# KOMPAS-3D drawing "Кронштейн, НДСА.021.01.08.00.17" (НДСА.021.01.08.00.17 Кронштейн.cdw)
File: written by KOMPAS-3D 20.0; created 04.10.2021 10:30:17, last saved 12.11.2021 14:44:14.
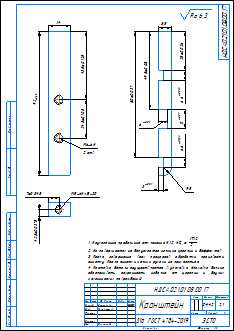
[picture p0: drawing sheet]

Sheet 1: A3, portrait

Document properties: Автор: adminzsc; Параметр неуказанной шероховатости: Ra 6,3; PLM_CDWXDTO: <item xmlns="http://appius.ru/pdm" xmlns:xs="http://www.w3.org/2001/XMLSchema" xmlns:xsi="http://www.w3.org/2001/XMLSchema-instance" xsi:type="item">  <element xmlns:d2p1="http://v8.1c.ru/8.1/data/enterprise/current-config" xsi:type="d2p1:CatalogRef.aps_Элемен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; PDM_DOCXDTO: <item xmlns="http://appius.ru/pdm" xmlns:xs="http://www.w3.org/2001/XMLSchema" xmlns:xsi="http://www.w3.org/2001/XMLSchema-instance" xsi:type="item">  <element xmlns:d2p1="http://v8.1c.ru/8.1/data/enterprise/current-config" xsi:type="d2p1:CatalogRef.aps_Элемен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; PDM_ITEMXDTO: <item xmlns="http://appius.ru/pdm" xmlns:xs="http://www.w3.org/2001/XMLSchema" xmlns:xsi="http://www.w3.org/2001/XMLSchema-instance" xsi:type="item">  <element xmlns:d2p1="http://v8.1c.ru/8.1/data/enterprise/current-config" xsi:type="d2p1:CatalogRef.aps_Элемен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; Масса: 0.0243981; PDM_DRAWINGXDTO: <item xmlns="http://appius.ru/pdm" xmlns:xs="http://www.w3.org/2001/XMLSchema" xmlns:xsi="http://www.w3.org/2001/XMLSchema-instance" xsi:type="item">  <element xmlns:d2p1="http://v8.1c.ru/8.1/data/enterprise/current-config" xsi:type="d2p1:CatalogRef.aps_Элемен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

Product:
- Part/product: Кронштейн  | designation НДСА.021.01.08.00.17
    Материал: Д16  ГОСТ 4784-2019 (density 2800 kg/m3)
    Масса: 0.0243981
    additional columns: <item xmlns="http://appius.ru/pdm" xmlns:xs="http://www.w3.org/2001/XMLSchema" x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; <item xmlns="http://appius.ru/pdm" xmlns:xs="http://www.w3.org/2001/XMLSchema" x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; <item xmlns="http://appius.ru/pdm" xmlns:xs="http://www.w3.org/2001/XMLSchema" x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
    source file: НДСА.021.01.08.00.17 Кронштейн.cdw

Title block, sheet 1: Наименование: Кронштейн; designation: НДСА.021.01.08.00.17; Материал: Д16  ГОСТ 4784-2019; Масса: 24,4 г; Количество листов документа: 1; organisation: ЭСТО; Форматы листов документа: A3; stored path: C:\Users\korychko\Desktop\PLM\НДСА.021.01.08.00.17 Кронштейн.cdw; Разработал: Васильева; Проверил: Горностаев; Утвердил: Белецкий; Разработал, date: 04.10.2021

Views: Вид 1, Спереди, Проекционный вид 3, Проекционный вид 4
Referenced files in C:\Users\vasilyeva\Desktop\PM_APPIUS\: НДСА.021.01.08.00.17 Кронштейн.m3d
Referenced files in C:\Users\korychko\Desktop\PLM\: НДСА.021.01.08.00.17 Кронштейн.m3d
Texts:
  JS12
  JS11
  JS9
  Ra 6,3
  НДСА.021.01.08.00.17 Кронштейн
Dimensions and other numbers on the sheet: 14; 43,5±0,125; 24,5±0,105; 92; 2 отв.; 7±0,045; 4,25±0,0375; 8,5; 25±0,026; 49,8±0,08; 80±0,037; 5; 6,6; 12; 3; 6; 2:1; 1; 24,4 г; 04.10.2021

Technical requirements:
  Неуказанные предельные отклонения H12, h12,    IT12 2 .
  На поверхностях не допускается наличие царапин и деффектов.
  После завершения всех процессов обработки произвести
  очистку. После очистки голыми руками не прикосаться.
  Поставка детали осуществляется в упаковке. Упаковка должна
  обеспечивать сохранность изделия от царапин и других
  механических повреждений.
